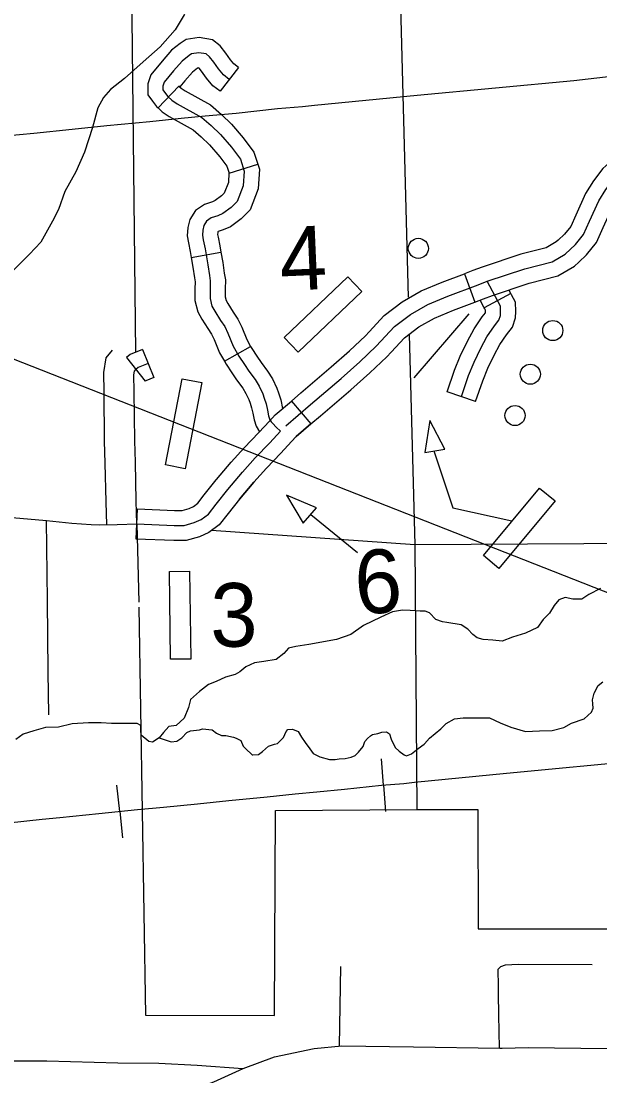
# Model space of a CAD drawing. Extents: x 22866 to 28196, y 1324810 to 1328105.
# Drawn here: x 25920.9 to 25990, y 1326217.3 to 1326343.3 of the extents above; entities that cross this region are included whole.
import ezdxf

# ---------------------------------------------------------------- set-up
doc = ezdxf.new("R2010")
doc.units = 0
for name, color, linetype in [('Level 15', 7, 'Continuous'), ('Level 31', 7, 'Continuous'), ('Level 32', 7, 'Continuous'), ('Level 33', 7, 'Continuous'), ('Level 35', 7, 'Continuous'), ('Level 40', 7, 'Continuous'), ('Level 5', 7, 'Continuous'), ('Level 56', 7, 'Continuous'), ('Level 6', 7, 'Continuous'), ('Page Text', 7, 'Continuous')]:
    doc.layers.add(name, color=color, linetype=linetype)

msp = doc.modelspace()

# ---------------------------------------------------------------- linework, layer by layer
at = {"layer": 'Level 15'}
for points in [[(25919.41, 1326212.66), (25920.94, 1326213.05), (25925.42, 1326213.84), (25928.65, 1326214), (25933.38, 1326214.01), (25935.53, 1326214.12), (25939.1, 1326214.79), (25940.06, 1326215.13), (25943.93, 1326216.56), (25947.41, 1326218.15), (25951.17, 1326219.57), (25955.89, 1326220.53), (25959.21, 1326220.87)], [(25959.21, 1326220.87), (25967.76, 1326220.75), (25978.07, 1326220.59), (25978.38, 1326220.58), (25981.49, 1326220.67), (25990.9, 1326220.53), (26009.29, 1326220.22), (26012.91, 1326220.14), (26030.97, 1326219.73)]]:
    msp.add_lwpolyline(points, dxfattribs=at)
at = {"layer": 'Level 31'}
for p, q in [((25973.85, 1326313.09), (25975.11, 1326309.72)), ((25975.11, 1326309.72), (25975.11, 1326309.72)), ((25935.38, 1326304.05), (25936.75, 1326300.71)), ((25953.18, 1326297.89), (25955.51, 1326295.15)), ((25934.65, 1326281.41), (25934.79, 1326285.01)), ((25934.79, 1326285.01), (25934.79, 1326285.01))]:
    msp.add_line(p, q, dxfattribs=at)
for points in [[(25945.76, 1326336.31), (25945.05, 1326336.86), (25944.45, 1326337.57), (25943.9, 1326338.38), (25943.38, 1326339.03), (25942.99, 1326339.35), (25942.13, 1326339.5), (25941.26, 1326339.37), (25940.95, 1326339.16), (25940.11, 1326338.48), (25939.09, 1326337.33), (25937.97, 1326335.97)], [(25937.97, 1326335.97), (25937.81, 1326335.5), (25937.81, 1326335.08), (25938.02, 1326334.79), (25938.41, 1326334.29), (25938.88, 1326333.85), (25939.54, 1326333.4), (25942.46, 1326331.78), (25943.61, 1326330.79), (25944.71, 1326329.72), (25946.02, 1326328.2), (25947.09, 1326326.78), (25947.54, 1326325.37)], [(25992.51, 1326327.49), (25992.19, 1326327.28), (25990.4, 1326325.66), (25989.29, 1326324.21), (25988.31, 1326322.67), (25987.16, 1326320.09), (25986.55, 1326318.73), (25985.82, 1326317.83), (25985.05, 1326317.11)], [(25947.54, 1326325.37), (25947.43, 1326323.62), (25946.7, 1326321.72), (25945.99, 1326321.02), (25945, 1326320.28), (25944.4, 1326320.02), (25943.61, 1326319.76), (25943.04, 1326319.37), (25942.73, 1326318.87), (25942.59, 1326318.32), (25942.54, 1326317.72), (25942.65, 1326317.14), (25942.86, 1326316.08), (25943.2, 1326314.17), (25943.38, 1326312.89), (25943.48, 1326312.25), (25943.46, 1326311.28), (25943.46, 1326310.13), (25943.69, 1326309.21), (25944.03, 1326308.61), (25944.71, 1326307.53), (25945.21, 1326306.78), (25945.6, 1326305.99), (25946.23, 1326304.45), (25946.91, 1326303.24), (25947.56, 1326302.25), (25948.08, 1326301.47)], [(25987.51, 1326314.49), (25988.45, 1326315.37), (25989.65, 1326316.83), (25990.45, 1326318.63), (25991.49, 1326320.97), (25992.24, 1326322.15), (25993.06, 1326323.21), (25994.4, 1326324.42), (25994.5, 1326324.48)], [(25985.05, 1326317.11), (25984.82, 1326316.9), (25983.64, 1326316.21), (25980.59, 1326315.42), (25975.99, 1326313.9), (25974.86, 1326313.47), (25973.85, 1326313.09)], [(25975.11, 1326309.72), (25976.14, 1326310.1), (25977.2, 1326310.51), (25981.6, 1326311.97), (25985.03, 1326312.85), (25986.99, 1326314), (25987.51, 1326314.49)], [(25935.38, 1326304.05), (25933.93, 1326303.45), (25933.47, 1326303.08), (25935.72, 1326300.27)], [(25936.07, 1326302.38), (25934.86, 1326301.88), (25934.59, 1326301.67)], [(25936.75, 1326300.71), (25935.78, 1326300.32), (25935.72, 1326300.27)], [(25948.08, 1326301.47), (25948.84, 1326300.45), (25949.34, 1326299.67), (25949.76, 1326298.75), (25949.94, 1326298.25), (25950.18, 1326297.57), (25950.33, 1326296.79), (25950.46, 1326296.11), (25950.62, 1326295.66), (25950.78, 1326295.4), (25950.96, 1326295.22), (25951.35, 1326294.77), (25951.87, 1326294.28)], [(25944.24, 1326288.53), (25946, 1326290.58), (25947.55, 1326292.31), (25949.28, 1326294.13), (25950.56, 1326295.5), (25951.26, 1326296.25), (25953.18, 1326297.89)], [(25955.51, 1326295.15), (25953.75, 1326293.65), (25953.19, 1326293.05), (25951.9, 1326291.66), (25950.19, 1326289.87), (25948.71, 1326288.21), (25946.97, 1326286.19)], [(25934.79, 1326285.01), (25939.21, 1326284.83), (25940.12, 1326284.83), (25940.97, 1326285.07), (25941.49, 1326285.3), (25942, 1326285.69), (25942.77, 1326286.68), (25944.19, 1326288.47), (25944.24, 1326288.53)], [(25946.97, 1326286.19), (25946.96, 1326286.18), (25945.61, 1326284.46), (25944.55, 1326283.1), (25943.33, 1326282.18), (25942.18, 1326281.67), (25940.62, 1326281.23), (25939.13, 1326281.23), (25934.65, 1326281.41)]]:
    msp.add_lwpolyline(points, dxfattribs=at)
at = {"layer": 'Level 32'}
for p, q in [((25946.87, 1326337.73), (25944.65, 1326334.89)), ((25937.26, 1326332.9), (25939.73, 1326335.52)), ((25945.73, 1326325.12), (25949.16, 1326326.2)), ((25941.21, 1326315.03), (25944.76, 1326315.66)), ((25979.41, 1326310.72), (25976.23, 1326309.04)), ((25945.18, 1326302.65), (25948.31, 1326304.42)), ((25975.19, 1326297.83), (25971.79, 1326299.01))]:
    msp.add_line(p, q, dxfattribs=at)
for points in [[(25946.87, 1326337.73), (25946.31, 1326338.17), (25945.89, 1326338.66), (25945.36, 1326339.45), (25944.66, 1326340.31), (25943.76, 1326341.03), (25942.15, 1326341.33), (25940.6, 1326341.09), (25939.88, 1326340.61), (25938.86, 1326339.79), (25937.73, 1326338.5), (25936.37, 1326336.86), (25936.01, 1326335.79), (25936.01, 1326334.49), (25936.58, 1326333.7), (25937.08, 1326333.08), (25937.26, 1326332.9)], [(25944.65, 1326334.89), (25943.8, 1326335.55), (25943.02, 1326336.47), (25942.45, 1326337.31), (25942.17, 1326337.66), (25942.1, 1326337.68), (25941.95, 1326337.65), (25941.36, 1326337.18), (25940.46, 1326336.16), (25939.85, 1326335.42), (25939.73, 1326335.52)], [(25939.73, 1326335.52), (25940.01, 1326335.26), (25940.48, 1326334.94), (25943.5, 1326333.27), (25944.83, 1326332.11), (25946.03, 1326330.95), (25947.42, 1326329.33), (25948.71, 1326327.62), (25949.16, 1326326.2)], [(25937.26, 1326332.9), (25937.75, 1326332.44), (25938.59, 1326331.87), (25941.43, 1326330.3), (25942.39, 1326329.46), (25943.4, 1326328.48), (25944.62, 1326327.06), (25945.47, 1326325.95), (25945.73, 1326325.12)], [(25949.16, 1326326.2), (25949.35, 1326325.6), (25949.21, 1326323.23), (25948.24, 1326320.72), (25947.17, 1326319.65), (25945.9, 1326318.71), (25945.04, 1326318.34), (25944.42, 1326318.13), (25944.4, 1326318.11), (25944.38, 1326318.03), (25944.36, 1326317.8), (25944.42, 1326317.48), (25944.63, 1326316.42), (25944.76, 1326315.66)], [(25945.72, 1326325.15), (25945.65, 1326324.01), (25945.16, 1326322.73), (25944.82, 1326322.39), (25944.09, 1326321.85), (25943.75, 1326321.7), (25942.81, 1326321.39), (25941.72, 1326320.64), (25941.04, 1326319.58), (25940.81, 1326318.61), (25940.73, 1326317.64), (25940.88, 1326316.81), (25941.09, 1326315.75), (25941.21, 1326315.03)], [(25944.76, 1326315.66), (25944.97, 1326314.46), (25945.16, 1326313.16), (25945.29, 1326312.37), (25945.26, 1326311.25), (25945.26, 1326310.35), (25945.38, 1326309.89), (25945.58, 1326309.53), (25946.23, 1326308.51), (25946.77, 1326307.67), (25947.24, 1326306.73), (25947.85, 1326305.23), (25948.31, 1326304.42)], [(25941.21, 1326315.03), (25941.42, 1326313.89), (25941.6, 1326312.62), (25941.68, 1326312.12), (25941.66, 1326311.3), (25941.66, 1326309.9), (25942.01, 1326308.53), (25942.49, 1326307.68), (25943.2, 1326306.56), (25943.64, 1326305.88), (25943.96, 1326305.25), (25944.6, 1326303.66), (25945.18, 1326302.65)], [(25973.49, 1326298.42), (25974.36, 1326300.95), (25975.01, 1326302.53), (25975.81, 1326304.21), (25976.55, 1326305.56), (25977.44, 1326306.88), (25977.98, 1326307.55), (25978.16, 1326308.13), (25978.18, 1326308.58), (25978.16, 1326309.23), (25977.89, 1326309.75), (25976.59, 1326312.2)], [(25975.19, 1326297.83), (25976.05, 1326300.31), (25976.65, 1326301.8), (25977.41, 1326303.39), (25978.09, 1326304.63), (25978.89, 1326305.81), (25979.6, 1326306.7), (25979.94, 1326307.82), (25979.98, 1326308.57), (25979.94, 1326309.7), (25979.48, 1326310.58), (25979.41, 1326310.72)], [(25975.19, 1326297.83), (25976.05, 1326300.31), (25976.65, 1326301.8), (25977.41, 1326303.39), (25978.09, 1326304.63), (25978.89, 1326305.81), (25979.6, 1326306.7), (25979.94, 1326307.82), (25979.98, 1326308.57), (25979.94, 1326309.7), (25979.48, 1326310.58), (25979.41, 1326310.72)], [(25979.41, 1326310.72), (25979.18, 1326311.16)], [(25976.23, 1326309.04), (25975.74, 1326309.96)], [(25971.79, 1326299.01), (25972.67, 1326301.58), (25973.36, 1326303.26), (25974.21, 1326305.03), (25975.01, 1326306.5), (25975.99, 1326307.95), (25976.36, 1326308.41), (25976.37, 1326308.45), (25976.38, 1326308.6), (25976.37, 1326308.76), (25976.3, 1326308.91), (25976.23, 1326309.04)], [(25948.31, 1326304.42), (25948.45, 1326304.18), (25949.06, 1326303.25), (25949.55, 1326302.51), (25950.33, 1326301.47), (25950.93, 1326300.53), (25951.42, 1326299.44), (25951.64, 1326298.86), (25951.92, 1326298.05), (25952.13, 1326296.99)], [(25945.18, 1326302.65), (25945.37, 1326302.31), (25946.06, 1326301.25), (25946.61, 1326300.43), (25947.36, 1326299.43), (25947.75, 1326298.81), (25948.09, 1326298.06), (25948.24, 1326297.65), (25948.43, 1326297.1), (25948.57, 1326296.44), (25948.72, 1326295.64), (25948.98, 1326294.89), (25949.38, 1326294.23)]]:
    msp.add_lwpolyline(points, dxfattribs=at)
at = {"layer": 'Level 33'}
for points in [[(25931.12, 1326283.11), (25931.05, 1326285.84), (25930.94, 1326290.49), (25930.86, 1326293.08), (25930.81, 1326298.96), (25930.75, 1326301.31), (25931.06, 1326303.05), (25931.82, 1326303.97)], [(25934.72, 1326283.21), (25934.65, 1326285.93), (25934.54, 1326290.59), (25934.46, 1326293.15), (25934.41, 1326299.02), (25934.36, 1326301.04), (25934.44, 1326301.48), (25934.59, 1326301.67)], [(25902.48, 1326285.35), (25911.31, 1326284.73), (25917.03, 1326284.2), (25923.93, 1326283.63), (25926.93, 1326283.31), (25929.26, 1326283.16), (25930.3, 1326283.1), (25932.37, 1326283.13), (25934.72, 1326283.21)], [(25924.19, 1326260.42), (25924.11, 1326265.55), (25924.03, 1326274.08), (25923.93, 1326283.63)], [(25934.72, 1326283.21), (25934.96, 1326273.87)], [(25958.94, 1326220.87), (25959.1, 1326230.33)], [(25978.03, 1326220.57), (25977.97, 1326224.57), (25977.92, 1326227.09), (25977.92, 1326228.6), (25977.87, 1326229.39), (25977.89, 1326230.04), (25978.21, 1326230.33), (25978.78, 1326230.54), (25980.27, 1326230.62), (25989.11, 1326230.59)], [(25947.36, 1326218.12), (25941.91, 1326218.51), (25937.34, 1326218.77), (25932.45, 1326218.79), (25923.94, 1326219.03), (25919.79, 1326219.03)]]:
    msp.add_lwpolyline(points, dxfattribs=at)
at = {"layer": 'Level 35'}
for points in [[(25958.05, 1326356.83), (25956.98, 1326355.84), (25955.86, 1326355.08), (25954.52, 1326354.59), (25952.73, 1326353.96), (25950.9, 1326353.02), (25948.26, 1326351.86), (25947.1, 1326351.19), (25945.27, 1326349.67), (25943.93, 1326348.42), (25942.27, 1326346.94), (25941.25, 1326345.82), (25940.35, 1326344.03), (25939.28, 1326342.24), (25937.49, 1326340.19), (25935.48, 1326338.4), (25933.25, 1326336.43), (25931.55, 1326335.09), (25930.74, 1326334.15), (25930.07, 1326332.9)], [(25930.07, 1326332.9), (25929.4, 1326330.57), (25928.47, 1326327.62), (25927.44, 1326325.29), (25926.1, 1326322.92), (25925.34, 1326320.77), (25924.62, 1326319.39), (25923.24, 1326316.88), (25921.9, 1326315.45), (25919.98, 1326313.53), (25918.77, 1326312.23)], [(25990.13, 1326275.48), (25988.71, 1326274.78), (25987.88, 1326274.22), (25987.73, 1326274.22), (25986.82, 1326274.22), (25985.88, 1326274.42), (25985.13, 1326274.15), (25984.58, 1326273.48), (25984.03, 1326272.57), (25983.28, 1326271.78), (25982.57, 1326270.84), (25981.16, 1326270.17), (25979.58, 1326269.7), (25978.36, 1326269.22), (25977.26, 1326269.34), (25976.08, 1326269.42), (25975.37, 1326269.62), (25974.86, 1326270.01), (25974.27, 1326270.64), (25973.48, 1326271.15), (25971.75, 1326271.43), (25971.24, 1326271.51), (25970.42, 1326271.78), (25969.67, 1326272.61), (25969.16, 1326272.81), (25968.57, 1326272.81), (25967.39, 1326272.88), (25966.44, 1326272.92), (25965.26, 1326272.73), (25963.88, 1326272.06), (25961.8, 1326271.07), (25960.3, 1326270.01), (25958.57, 1326269.42), (25955.27, 1326268.79), (25953.71, 1326268.59), (25952.84, 1326268.36), (25952.29, 1326267.73), (25951.35, 1326267.02), (25949.89, 1326266.78), (25948.79, 1326266.62), (25947.73, 1326266.15), (25947.02, 1326265.56), (25946.47, 1326265.21), (25945.29, 1326264.89), (25944.19, 1326264.38), (25943.28, 1326264.02), (25942.18, 1326263.2), (25941.12, 1326262.25), (25940.88, 1326261.27), (25940.37, 1326260.01), (25939.42, 1326259.14), (25938.52, 1326259.02)], [(25965.59, 1326256.52), (25966.05, 1326256.05), (25966.64, 1326255.61), (25966.92, 1326255.49), (25967.55, 1326255.73), (25968.33, 1326256.4), (25969.04, 1326256.91), (25969.08, 1326256.95), (25969.67, 1326257.62), (25971.05, 1326258.72), (25971.68, 1326259.39), (25972.66, 1326259.91), (25973.72, 1326260.06), (25976.87, 1326260.06), (25978.13, 1326259.47), (25979.39, 1326258.92), (25981.16, 1326258.41), (25982.81, 1326258.49), (25984.35, 1326258.53), (25985.72, 1326258.88), (25986.63, 1326259.43), (25988.16, 1326259.94), (25989.03, 1326260.73), (25989.23, 1326261.2), (25989.19, 1326261.72), (25989.15, 1326262.19), (25989.34, 1326262.98), (25989.82, 1326263.92), (25990.41, 1326264.36)], [(25938.52, 1326259.02), (25937.9, 1326258.29), (25937.39, 1326257.66), (25936.6, 1326257.15), (25936.13, 1326257.23), (25935.23, 1326257.98), (25935.19, 1326258.57), (25935.19, 1326259.12), (25934.75, 1326259.39), (25933.77, 1326259.39), (25931.69, 1326259.39), (25930.43, 1326259.47), (25928.93, 1326259.47), (25927, 1326259.35), (25925.35, 1326258.92), (25923.78, 1326258.88), (25922.4, 1326258.49), (25921.14, 1326258.09), (25920.24, 1326257.46)], [(25937.39, 1326257.66), (25938.8, 1326257.19), (25939.51, 1326257.27), (25940.1, 1326257.66), (25940.69, 1326258.29), (25941.12, 1326258.49), (25942.18, 1326258.61), (25942.54, 1326258.72), (25943.72, 1326258.61), (25944.23, 1326258.21), (25944.82, 1326257.94), (25945.33, 1326257.94), (25946.27, 1326257.74), (25946.59, 1326257.62), (25947.14, 1326257.35), (25947.42, 1326256.68), (25947.69, 1326256.4), (25948.48, 1326255.61), (25948.56, 1326255.61), (25949.26, 1326255.65), (25949.74, 1326256.01), (25950.44, 1326256.68), (25951.15, 1326256.91), (25951.51, 1326256.99), (25952.22, 1326257.7), (25952.57, 1326258.41), (25952.77, 1326258.65), (25953.32, 1326258.68), (25953.99, 1326258.41), (25954.38, 1326257.74), (25954.81, 1326257.11), (25955.4, 1326256.36), (25955.8, 1326255.77), (25956.58, 1326255.38), (25957.72, 1326255.06), (25958.39, 1326255.06), (25958.9, 1326255.14), (25959.61, 1326255.18), (25960.32, 1326255.34), (25960.79, 1326255.53), (25961.19, 1326255.93), (25961.74, 1326256.64), (25961.97, 1326257.23), (25962.29, 1326257.58), (25962.64, 1326257.9), (25962.88, 1326258.05), (25963.51, 1326258.17), (25963.98, 1326258.33), (25964.53, 1326258.37), (25964.92, 1326258.13), (25965.12, 1326257.5), (25965.59, 1326256.52)]]:
    msp.add_lwpolyline(points, dxfattribs=at)
at = {"layer": 'Level 40'}
for p, q in [((25964.18, 1326252.01), (25963.93, 1326255.17)), ((25964.18, 1326252.01), (25963.93, 1326255.17)), ((25932.66, 1326248.87), (25932.33, 1326252.02)), ((25932.66, 1326248.87), (25932.33, 1326252.02)), ((25964.18, 1326252.01), (25964.44, 1326248.85)), ((25964.18, 1326252.01), (25964.44, 1326248.85)), ((25932.66, 1326248.87), (25932.98, 1326245.72)), ((25932.66, 1326248.87), (25932.98, 1326245.72))]:
    msp.add_line(p, q, dxfattribs=at)
for points in [[(25918.97, 1326329.58), (25922.41, 1326329.89), (25926.97, 1326330.36), (25931.14, 1326330.79), (25936.26, 1326331.3), (25940, 1326331.68), (25942.88, 1326331.95), (25946.57, 1326332.29), (25951.52, 1326332.82), (25954.5, 1326333.06), (25955.93, 1326333.24), (25968.22, 1326334.43), (25986.93, 1326336.2), (25996.87, 1326337.32), (26005.7, 1326338.21), (26019.21, 1326339.6), (26034.58, 1326340.98), (26039.99, 1326341.64), (26046.34, 1326342.26), (26047.31, 1326342.41), (26055.16, 1326343.1)], [(25955.93, 1326333.24), (25968.22, 1326334.43), (25986.93, 1326336.2), (25996.87, 1326337.32), (26005.7, 1326338.21), (26019.21, 1326339.6), (26034.58, 1326340.98), (26039.99, 1326341.64), (26046.34, 1326342.26), (26047.31, 1326342.41), (26055.16, 1326343.1)], [(25869.51, 1326324.61), (25873.48, 1326324.96), (25879.86, 1326325.57), (25883.12, 1326325.91), (25886.27, 1326326.26), (25889.86, 1326326.58), (25895.54, 1326327.17), (25901.72, 1326327.82), (25906.21, 1326328.29), (25908.61, 1326328.51), (25913.77, 1326329.04), (25918.97, 1326329.58), (25922.41, 1326329.89), (25926.97, 1326330.36), (25931.14, 1326330.79), (25936.26, 1326331.3), (25940, 1326331.68), (25942.88, 1326331.95), (25946.57, 1326332.29), (25951.52, 1326332.82), (25954.5, 1326333.06), (25955.93, 1326333.24)], [(25975.5, 1326311.79), (25976.59, 1326312.2), (25981.09, 1326313.7), (25984.34, 1326314.53), (25985.91, 1326315.45), (25987.13, 1326316.6), (25988.1, 1326317.78), (25988.8, 1326319.36), (25989.9, 1326321.82), (25990.76, 1326323.18), (25991.73, 1326324.44), (25993.3, 1326325.85), (25995.23, 1326327.13), (25997.51, 1326328.47), (25999.66, 1326329.64)], [(25962.47, 1326306.17), (25964.27, 1326308.13), (25966.43, 1326309.76), (25968.69, 1326311.05), (25971.2, 1326312.1), (25973.85, 1326313.09)], [(25952.5, 1326294.95), (25955.48, 1326297.49), (25959.12, 1326300.6), (25961.36, 1326302.57), (25963.32, 1326304.43), (25965.49, 1326306.79), (25967.42, 1326308.25), (25969.49, 1326309.43), (25971.87, 1326310.43), (25975.5, 1326311.79)], [(25965.12, 1326303.73), (25966.7, 1326305.45), (25968.42, 1326306.75), (25970.28, 1326307.81), (25972.53, 1326308.75), (25975.11, 1326309.72)], [(25953.18, 1326297.89), (25954.31, 1326298.86), (25957.94, 1326301.96), (25960.14, 1326303.9), (25962.04, 1326305.7), (25962.47, 1326306.17)], [(25955.51, 1326295.15), (25956.65, 1326296.12), (25960.3, 1326299.24), (25962.57, 1326301.25), (25964.6, 1326303.17), (25965.12, 1326303.73)], [(25934.72, 1326283.21), (25939.17, 1326283.03), (25940.37, 1326283.03), (25941.57, 1326283.37), (25942.41, 1326283.74), (25943.27, 1326284.39), (25944.19, 1326285.57), (25945.57, 1326287.32), (25947.35, 1326289.39), (25948.87, 1326291.09), (25950.59, 1326292.9), (25951.87, 1326294.28)], [(25946.97, 1326286.19), (25948.71, 1326288.21), (25950.19, 1326289.87), (25951.9, 1326291.66), (25953.19, 1326293.05), (25953.75, 1326293.65), (25955.51, 1326295.15)], [(25967.9, 1326252.36), (25978.9, 1326253.43), (25995.65, 1326255.02), (26004.54, 1326256.02), (26012.44, 1326256.82), (26024.54, 1326258.06), (26038.3, 1326259.3), (26043.14, 1326259.89), (26048.83, 1326260.44), (26049.69, 1326260.58), (26056.72, 1326261.2), (26063.31, 1326261.82), (26068.77, 1326262.47), (26076.77, 1326263.2), (26084.49, 1326263.82), (26086.61, 1326264.03), (26086.71, 1326264.03)], [(25919.37, 1326247.52), (25923.39, 1326247.94), (25925.53, 1326248.13), (25930.16, 1326248.61), (25934.81, 1326249.09), (25937.89, 1326249.37), (25941.97, 1326249.79), (25945.7, 1326250.18), (25950.29, 1326250.63), (25953.64, 1326250.97), (25956.21, 1326251.22), (25959.52, 1326251.52), (25963.95, 1326251.99), (25966.61, 1326252.21), (25967.9, 1326252.36), (25978.9, 1326253.43), (25995.65, 1326255.02)], [(25919.37, 1326247.52), (25923.39, 1326247.94), (25925.53, 1326248.13), (25930.16, 1326248.61), (25934.81, 1326249.09), (25937.89, 1326249.37), (25941.97, 1326249.79), (25945.7, 1326250.18), (25950.29, 1326250.63), (25953.64, 1326250.97), (25956.21, 1326251.22), (25959.52, 1326251.52), (25963.95, 1326251.99), (25966.61, 1326252.21), (25967.9, 1326252.36), (25978.9, 1326253.43), (25995.65, 1326255.02)], [(25890.53, 1326244.65), (25894.09, 1326244.96), (25899.81, 1326245.5), (25902.72, 1326245.8), (25905.54, 1326246.12), (25908.75, 1326246.4), (25913.83, 1326246.93), (25919.37, 1326247.52), (25923.39, 1326247.94), (25925.53, 1326248.13), (25930.16, 1326248.61), (25934.81, 1326249.09), (25937.89, 1326249.37), (25941.97, 1326249.79), (25945.7, 1326250.18), (25950.29, 1326250.63), (25953.64, 1326250.97), (25956.21, 1326251.22), (25959.52, 1326251.52), (25963.95, 1326251.99), (25966.61, 1326252.21), (25967.9, 1326252.36)]]:
    msp.add_lwpolyline(points, dxfattribs=at)
at = {"layer": 'Level 5'}
for points in [[(25965.46, 1326373.77), (25967.13, 1326310.29)], [(25967.25, 1326305.86), (25967.91, 1326280.73)], [(25967.91, 1326280.73), (25943.65, 1326282.42)], [(26028.55, 1326281.08), (25967.91, 1326280.73)], [(25967.91, 1326280.73), (25968.18, 1326249.09)]]:
    msp.add_lwpolyline(points, dxfattribs=at)
at = {"layer": 'Level 56'}
for p, q in [((25970.19, 1326291.95), (25972.47, 1326285.12)), ((25955.49, 1326284.33), (25961.07, 1326279.78)), ((25972.47, 1326285.12), (25979.51, 1326283.6))]:
    msp.add_line(p, q, dxfattribs=at)
for points in [[(25953.97, 1326303.74), (25952.32, 1326305.49), (25959.94, 1326312.71), (25961.59, 1326310.96)], [(25940.47, 1326289.79), (25938.12, 1326290.26), (25940.13, 1326300.56), (25942.49, 1326300.1)], [(25969.11, 1326291.76), (25971.53, 1326292.14), (25969.74, 1326295.58)], [(25954.57, 1326283.29), (25956.18, 1326285.14), (25952.6, 1326286.63)], [(25982.84, 1326287.5), (25984.69, 1326285.96), (25977.96, 1326277.89), (25976.12, 1326279.43)], [(25938.61, 1326277.54), (25941.01, 1326277.57), (25941.15, 1326267.07), (25938.75, 1326267.04)]]:
    msp.add_lwpolyline(points, close=True, dxfattribs=at)
msp.add_lwpolyline([(25974.37, 1326308.29), (25967.81, 1326300.66)], dxfattribs=at)
for centre in [(25968.35, 1326316.13), (25984.41, 1326306.31), (25981.73, 1326301.1), (25979.9, 1326296.16)]:
    msp.add_circle(centre, 1.2, dxfattribs=at)
at = {"layer": 'Level 6'}
for points in [[(25933.76, 1326376.32), (25934.57, 1326303.71)], [(25934.95, 1326273.27), (25935.73, 1326224.53), (25951.18, 1326224.51), (25951.27, 1326248.99), (25968.18, 1326249.09), (25975.47, 1326249.09), (25975.5, 1326234.86), (25991.12, 1326234.85), (25991.25, 1326220.45)]]:
    msp.add_lwpolyline(points, dxfattribs=at)
at = {"layer": 'Page Text'}
msp.add_lwpolyline([(25620.91, 1326420.53), (26211.65, 1326188.26)], dxfattribs=at)

# ---------------------------------------------------------------- texts
at = {"layer": 'Level 56'}
for s, rotation, p in [('4', 2.4392, (25951.91, 1326311.05)), ('6', 3.1254, (25960.92, 1326272.41))]:
    msp.add_text(s, height=7.6, rotation=rotation, dxfattribs=at).set_placement(p)
msp.add_text('3', height=7.6, dxfattribs=at).set_placement((25943.49, 1326268.55))

doc.saveas('drawing.dxf')
